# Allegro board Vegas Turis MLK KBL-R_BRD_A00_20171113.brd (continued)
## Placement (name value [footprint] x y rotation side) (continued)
PG5121  GAP-CLOSE-PWR-3-GP  [GAP-CLOSE-PWR-3]  58.35 36.5 0 top
PG5122  GAP-CLOSE-PWR-3-GP  [GAP-CLOSE-PWR-3]  58.35 35.56 0 top
PG5123  GAP-CLOSE-PWR-3-GP  [GAP-CLOSE-PWR-3]  58.35 34.62 0 top
PG5124  GAP-CLOSE-PWR-3-GP  [GAP-CLOSE-PWR-3]  58.34 33.68 0 top
PG5125  GAP-CLOSE-PWR-3-GP  [GAP-CLOSE-PWR-3]  58.1 38.89 0 bottom
PG5126  GAP-CLOSE-PWR-3-GP  [GAP-CLOSE-PWR-3]  58.09 37.94 0 bottom
PG5127  GAP-CLOSE-PWR-3-GP  [GAP-CLOSE-PWR-3]  58.09 37 0 bottom
PG5128  GAP-CLOSE-PWR-3-GP  [GAP-CLOSE-PWR-3]  58.09 36.06 0 bottom
PG5129  GAP-CLOSE-PWR-3-GP  [GAP-CLOSE-PWR-3]  58.1 35.1 0 bottom
PG5130  GAP-CLOSE-PWR-3-GP  [GAP-CLOSE-PWR-3]  58.1 34.17 0 bottom
PG5151  -  [GAP-CLOSE-PWR]  135.59 29.98 180 bottom
PG5152  -  [GAP-CLOSE-PWR]  135.59 29.22 180 bottom
PG5301  GAP-CLOSE-PWR-3-GP  [GAP-CLOSE-PWR-3]  184.97 69.77 180 bottom
PG5302  GAP-CLOSE-PWR-3-GP  [GAP-CLOSE-PWR-3]  184.97 70.54 180 bottom
PG5303  GAP-CLOSE-PWR-3-GP  [GAP-CLOSE-PWR-3]  184.96 68.83 180 bottom
PG5304  GAP-CLOSE-PWR-3-GP  [GAP-CLOSE-PWR-3]  168.03 73.97 180 bottom
PG5305  GAP-CLOSE-PWR-3-GP  [GAP-CLOSE-PWR-3]  168.03 74.73 180 bottom
PG5306  GAP-CLOSE-PWR-3-GP  [GAP-CLOSE-PWR-3]  168.03 75.49 180 bottom
PG5307  GAP-CLOSE-PWR-3-GP  [GAP-CLOSE-PWR-3]  168.03 76.25 180 bottom
PG5308  GAP-CLOSE-PWR-3-GP  [GAP-CLOSE-PWR-3]  168.03 77.01 180 bottom
PG5309  GAP-CLOSE-PWR-3-GP  [GAP-CLOSE-PWR-3]  168.03 77.01 180 top
PG5310  GAP-CLOSE-PWR-3-GP  [GAP-CLOSE-PWR-3]  175.04 71.83 180 top
PG5311  GAP-CLOSE-PWR-3-GP  [GAP-CLOSE-PWR-3]  168.03 76.25 180 top
PG5312  GAP-CLOSE-PWR-3-GP  [GAP-CLOSE-PWR-3]  168.03 75.49 180 top
PG5313  GAP-CLOSE-PWR-3-GP  [GAP-CLOSE-PWR-3]  168.03 74.73 180 top
PG5314  GAP-CLOSE-PWR-3-GP  [GAP-CLOSE-PWR-3]  168.03 73.97 180 top
PG5405  -  [GAP-CLOSE-PWR]  164.27 72.39 90 bottom
PG5406  -  [GAP-CLOSE-PWR]  163.51 72.39 90 bottom
PG5407  -  [GAP-CLOSE-PWR]  162.75 72.39 90 bottom
PG8501  -  [GAP-CLOSE-PWR]  163.61 99.63 0 bottom
PG8502  -  [GAP-CLOSE-PWR]  163.61 98.86 0 bottom
PG8503  -  [GAP-CLOSE-PWR]  163.61 98.1 0 bottom
PG8504  -  [GAP-CLOSE-PWR]  167.08 95.83 90 bottom
PG8505  -  [GAP-CLOSE-PWR]  166.32 95.83 90 bottom
PG8506  -  [GAP-CLOSE-PWR]  165.56 95.83 90 bottom
PG8507  GAP-CLOSE-PWR-3-GP  [GAP-CLOSE-PWR-3]  178.22 114.12 180 bottom
PG8508  GAP-CLOSE-PWR-3-GP  [GAP-CLOSE-PWR-3]  180.74 114.12 0 bottom
PG8509  GAP-CLOSE-PWR-3-GP  [GAP-CLOSE-PWR-3]  178.54 100.61 180 bottom
PG8510  GAP-CLOSE-PWR-3-GP  [GAP-CLOSE-PWR-3]  180.91 100.64 0 bottom
PG8511  -  [GAP-CLOSE-PWR]  163.96 119.89 0 top
PG8512  -  [GAP-CLOSE-PWR]  163.96 119.13 0 top
PG8513  -  [GAP-CLOSE-PWR]  163.96 118.37 0 top
PG8514  -  [GAP-CLOSE-PWR]  163.96 117.6 0 top
PG8515  -  [GAP-CLOSE-PWR]  163.96 116.84 0 top
PG8516  -  [GAP-CLOSE-PWR]  163.96 116.08 0 top
PG8601  -  [GAP-CLOSE-PWR]  135.13 151.55 0 bottom
PG8602  -  [GAP-CLOSE-PWR]  135.13 152.31 0 bottom
PG8603  -  [GAP-CLOSE-PWR]  148.93 150.04 0 bottom
PG8604  -  [GAP-CLOSE-PWR]  148.95 149.07 0 bottom
PG8651  GAP-CLOSE-PWR-3-GP  [GAP-CLOSE-PWR-3]  189.92 173.05 270 bottom
PG8652  GAP-CLOSE-PWR-3-GP  [GAP-CLOSE-PWR-3]  190.88 173.04 270 bottom
PG8653  GAP-CLOSE-PWR-3-GP  [GAP-CLOSE-PWR-3]  197 154.13 180 bottom
PG8655  GAP-CLOSE-PWR-3-GP  [GAP-CLOSE-PWR-3]  198.12 174.41 270 top
PL4401  COIL-4D7UH-33-GP  [L7066-1830-UH119]  139.68 163.98 270 bottom
PL4501  IND-2D2UH-46-GP-U1  [L7066-1830-UH119]  52.53 60.14 180 bottom
PL4502  IND-3D3UH-57-GP-U  [L7066-1830-UH119]  43 60.14 0 bottom
PL4701  COIL-D15UH-2-GP  [L7366-1930H158]  103.66 118.21 180 bottom
PL4801  COIL-D15UH-2-GP  [L7366-1930H158]  123.04 117.99 180 bottom
PL4802  COIL-D15UH-2-GP  [L7366-1930H158]  113.19 117.96 180 bottom
PL5001  IND-D47UH-22-GP-U  [L7066-1830-UH119]  135.87 117.97 180 bottom
PL5101  COIL-D68UH-5-GP-U  [L7066-1830-UH119]  48.68 31.52 0 bottom
PL5301  COIL-1UH-34-GP-U1  [L7066-1830-UH119]  174.2 75.41 90 bottom
PL8501  IND-D33UH-7-GP-U  [L7066-1830-UH119]  179.5 114.12 270 bottom
PL8502  IND-D33UH-7-GP-U  [L7066-1830-UH119]  179.73 100.77 270 bottom
PL8601  IND-1UH-281-GP  [L3030-3009H63]  145.5 152.33 270 bottom
PL8651  IND-D68UH-36-GP-U  [L686647-127318H119]  194.92 158.71 180 bottom
PQ4301  DMN5L06K-7-GP  [SOT23DGS2D4H48]  61.32 173.71 90 bottom
PQ4302  LMBT3904LT1G-GP  [SOT23CBE2D4H44]  57.49 173.69 90 bottom
PQ4304  LMUN5212T1G-GP  [SOT323CBE2D2H40]  82.53 160.19 0 top
PQ4305  LTA024EUB-FS8-GP  [SC70-2D2-312H44]  81.02 164.23 0 top
PQ4306  2N7002KDW-GP  [SOT-363H44]  77.63 164.72 90 top
PQ4401  AON7403-GP-U  [PPAK-8P-3232H36]  142.25 161.9 0 top
PQ4402  2N7002K-2-GP  [SOT23DGS2D4H44]  123.35 182.12 90 top
PQ4405  2N7002KDW-GP  [SOT-363H44]  120.8 169.51 180 top
PQ4406  2N7002KDW-GP  [SOT-363H44]  127.16 179.43 90 top
PQ4409  MMBT3906-7F-GP  [SOT23CBE2D4H44]  123.48 176.71 0 top
PQ4410  AON7403-GP-U  [PPAK-8P-3232H36]  117.28 163.35 90 top
PQ4412  2N7002K-2-GP  [SOT23DGS2D4H44]  119.01 175.01 180 top
PQ4415  LMUN5212T1G-GP  [SOT323CBE2D2H40]  139.73 172.62 180 top
PQ4416  LTA024EUB-FS8-GP  [SC70-2D2-312H44]  138.23 168.12 90 top
PQ8501  2N7002KDW-GP  [SOT-363H44]  161.62 104.81 270 top
PQ8604  2N7002KDW-GP  [SOT-363H44]  146.01 137.77 270 bottom
PQ8607  DMP2130L-7-GP  [SOT23DGS2D4H48]  146.25 139.4 270 top
PQ8608  2N7002K-2-GP  [SOT23DGS2D4H44]  143.34 143.11 180 top
PQ8609  PJA3419-GP  [SOT23DGS2D4H44]  145.84 141.11 90 bottom
PR4302  15KR2F-GP  [R402H16]  56.59 171.45 90 bottom
PR4303  10KR2J-L-GP  [R402H15]  60.81 171.49 270 bottom
PR4304  2K2R2J-L1-GP  [R402H16]  65.03 173.36 270 bottom
PR4305  33R2J-2-GP  [R402H16]  65.03 174.2 270 bottom
PR4306  33R2J-2-GP  [R402H16]  63.76 173.76 0 bottom
PR4307  240KR3-GP  [R603H22]  83.17 167.59 0 top
PR4308  47KR3J-L-GP  [R603H22]  83.26 164.73 0 top
PR4309  100KR2J-1-GP  [R402H16]  59.81 170 90 bottom
PR4312  100KR2J-1-GP  [R402H16]  77.68 168.35 0 top
PR4313  -  [0R0402-PAD]  76.31 167.01 270 top
PR4314  3K3R6J-GP  [R1206H28]  79.25 168.48 0 top
PR4317  -  [0R0603-PAD]  63.82 176.71 0 top
PR4401  200KR2F-L-GP  [R402H16]  138.19 175.76 270 top
PR4402  200KR2F-L-GP  [R402H16]  138.54 177.19 180 top
PR4403  95K3R2F-GP  [R402H16]  136.18 175.01 270 top
PR4404  82K5R2F-GP  [R402H16]  136.18 178.35 270 top
PR4405  147KR2F-GP  [R402H16]  138.4 179.3 270 bottom
PR4406  -  [0R0402-PAD]  136.18 177.59 90 top
PR4407  100R2F-L3-GP  [R402H16]  138.48 179.3 90 top
PR4408  0R2J-2-GP  [R402H16]  124.24 179.45 0 top
PR4409  100KR2F-L3-GP  [R402H16]  139.12 177.07 0 bottom
PR4410  7K15R2F-L-GP  [R402H16]  138.18 171.14 270 bottom
PR4411  1KR2F-L1-GP  [R402H15]  134.08 178.86 0 top
PR4412  NTC-220K-1-GP-U  [NTC-402H24-U]  138.28 170.21 90 bottom
PR4413  100KR2F-L3-GP  [R402H16]  127.92 176.53 90 top
PR4414  1MR2J-1-GP  [R402H16]  119.89 178.44 0 top
PR4415  -  [0R0402-PAD]  120.4 181.05 180 top
PR4416  18K7R2F-GP  [R402H16]  131.48 181.45 90 bottom
PR4417  100KR2J-1-GP  [R402H16]  130.26 176.74 90 top
PR4418  191KR2F-1-GP  [R402H16]  121.62 172.32 90 top
PR4420  10KR2F-L1-GP  [R402H15]  118.83 168.19 180 top
PR4422  10KR2F-L1-GP  [R402H15]  119.62 166.84 90 top
PR4426  D01R3721F-GP-U  [R3720H40]  122.66 163.63 90 top
PR4428  0R0603-PAD-1-GP-U  [0R0603-PAD-U]  131.13 171.62 180 bottom
PR4431  100KR2J-1-GP  [R402H16]  121.67 179.45 0 top
PR4434  300KR2F-L-GP  [R402H16]  133.23 178.87 180 top
PR4435  10KR2F-L1-GP  [R402H15]  133.16 180.64 270 bottom
PR4437  2R2F-GP  [R402H16]  136.46 173.68 90 top
PR4438  4D7R3F-L-GP  [R603H22]  135.12 170.93 90 bottom
PR4439  100KR2F-L3-GP  [R402H16]  138.3 177.07 0 bottom
PR4440  20KR3J-1-GP  [R603H22]  118.59 171.98 270 top
PR4441  100KR2J-1-GP  [R402H16]  119.62 165.98 270 top
PR4443  D01R3721F-GP-U  [R3720H40]  143.49 170.06 0 bottom
PR4444  1KR2J-1-GP  [R402H16]  121.32 175.8 0 top
PR4445  470KR2J-L1-GP  [R402H15]  118.41 170.89 270 top
PR4449  10KR2F-L1-GP  [R402H15]  134.84 180.64 90 bottom
PR4450  100KR2F-L3-GP  [R402H16]  135.5 181.55 270 bottom
PR4451  100KR2F-L3-GP  [R402H16]  131.5 179 90 top
PR4452  150KR2F-L-GP  [R402H16]  130.65 182.64 270 bottom
PR4453  10KR2F-L1-GP  [R402H15]  126.12 175.57 270 top
PR4454  100R5F-2-GP  [R805H24]  128.56 173.87 270 top
PR4455  680KR2F-GP  [R402H16]  122.54 179.45 180 top
PR4456  2R2F-GP  [R402H16]  138.47 173.12 0 bottom
PR4457  0R0402-PAD-1-GP  [0R0402-PAD]  139.29 173.12 0 bottom
PR4458  -  [0R0402-PAD]  130.54 182.68 90 top
PR4459  -  [0R0402-PAD]  125.94 172.34 270 top
PR4462  -  [0R0402-PAD]  123.4 179.45 0 top
PR4467  0R0402-PAD-1-GP  [0R0402-PAD]  128.12 179.59 270 bottom
PR4468  2R2F-GP  [R402H16]  128.13 178.71 270 bottom
PR4470  -  [0R0402-PAD]  133.38 181.88 180 bottom
PR4471  -  [0R0402-PAD]  134.24 181.89 180 bottom
PR4472  100KR2F-L3-GP  [R402H16]  127.89 181.37 90 top
PR4474  -  [0R0402-PAD]  131.58 177.27 180 top
PR4475  -  [0R0402-PAD]  137.67 182.13 90 bottom
PR4476  -  [0R0402-PAD]  137.67 181.31 90 bottom
PR4477  1KR2F-L1-GP  [R402H15]  128.12 175.39 270 bottom
PR4478  100KR2J-1-GP  [R402H16]  125.94 182.62 180 top
PR4481  0R2J-2-GP  [R402H16]  135.05 167.88 180 top
PR4501  0R2J-2-GP  [R402H16]  43.48 79.83 270 top
PR4502  -  [0R0402-PAD]  52.76 79.06 0 top
PR4503  -  [0R0402-PAD]  44.27 76.27 90 top
PR4504  -  [0R0402-PAD]  44.02 77.54 0 top
PR4505  -  [0R0402-PAD]  48.44 79.96 180 top
PR4512  6K65R2F-GP  [R402H16]  46.18 79.8 0 top
PR4517  127KR2F-L-GP  [R402H16]  44.91 77.54 180 top
PR4523  10KR2F-L1-GP  [R402H15]  47.04 78.94 180 top
PR4524  1D5R3-GP  [R603H22]  53.64 73.47 90 top
PR4525  0R2J-2-GP  [R402H16]  50.98 79.06 0 top
PR4526  10KR2F-2-GP  [R402H16]  49.71 80.41 90 top
PR4527  15K4R2F-GP  [R402H16]  49.71 79.45 270 top
PR4528  1D5R3-GP  [R603H22]  43.48 72.96 90 top
PR4529  2D2R5F-2-GP  [R805H24]  57.25 64.89 0 bottom
PR4530  0R2J-2-GP  [R402H16]  43.48 78.94 90 top
PR4531  127KR2F-L-GP  [R402H16]  51.87 79.06 180 top
PR4533  2D2R5F-2-GP  [R805H24]  46.8 65.63 270 bottom
PR4534  100KR2J-1-GP  [R402H16]  44.27 75.38 90 top
PR4535  0R2J-2-GP  [R402H16]  45.67 81.07 270 top
PR4601  0R0402-PAD-1-GP  [0R0402-PAD]  114.83 142.23 270 top
PR4602  0R0402-PAD-1-GP  [0R0402-PAD]  114.83 143.01 270 top
PR4603  1KR2F-L1-GP  [R402H15]  126.15 149.48 0 top
PR4604  100R2F-L3-GP  [R402H16]  121.98 149.46 0 top
PR4605  75R2F-2-GP  [R402H16]  123.38 149.46 0 top
PR4606  45D3R2F-L-GP  [R402H16]  124.76 149.48 0 top
PR4607  100R2F-L3-GP  [R402H16]  126.15 147.77 0 top
PR4608  90K9R2F-GP  [R402H16]  127.1 143.47 270 top
PR4609  10KR2F-L1-GP  [R402H15]  127.49 147.81 0 top
PR4610  1R2J-GP  [R402H16]  121.2 147.73 0 top
PR4611  NTC-10K-29-GP-U  [NTC-402H22-U]  130.9 119.06 180 bottom
PR4612  0R0402-PAD-1-GP  [0R0402-PAD]  117.33 148.3 270 top
PR4613  0R2J-L-GP  [R402H15]  114.41 147.31 270 top
PR4614  0R2J-L-GP  [R402H15]  127.09 144.26 90 bottom
PR4615  1KR2F-L1-GP  [R402H15]  116.01 145.5 90 top
PR4616  5K76R2F-2-GP  [R402H16]  127.11 142.64 270 bottom
PR4617  NTC-470K-9-GP-U  [NTC-402H24-U]  127.9 122.3 0 bottom
PR4618  11KR2F-L-GP  [R402H16]  114.47 144.72 90 top
PR4620  392R2F-GP  [R402H16]  116.69 144.61 90 top
PR4621  27K4R2F-GP  [R402H16]  129.48 143.53 270 top
PR4622  10R2F-L1-GP  [R402H16]  121.99 147.72 0 top
PR4623  0R0402-PAD-1-GP  [0R0402-PAD]  123.36 147.74 0 top
PR4624  49D9R2F-L1-GP  [R402H16]  124.72 147.75 0 top
PR4625  2K61R2F-1-GP  [R402H16]  112.82 143.74 90 top
PR4626  3K3R2F-2-GP  [R402H16]  127.1 142.66 270 top
PR4627  100R2F-L3-GP  [R402H16]  117.68 142.53 0 top
PR4628  9K31R2F-GP  [R402H16]  120.05 144.82 0 top
PR4629  88K7R2F-GP  [R402H16]  120.83 144.82 0 top
PR4630  2KR2F-L1-GP  [R402H16]  127.72 139.48 90 bottom
PR4631  100R2F-L3-GP  [R402H16]  130.47 140.08 0 bottom
PR4632  1KR2F-3-GP  [R402H16]  116.42 143.12 270 bottom
PR4633  3K01R2F-3-GP  [R402H16]  127.7 140.27 90 bottom
PR4635  1KR2F-L1-GP  [R402H15]  121.1 133.14 90 top
PR4636  499R2F-2-GP  [R402H16]  127.42 141.87 90 bottom
PR4637  1K69R2F-2-GP  [R402H16]  116.29 141.35 90 bottom
PR4638  2KR2F-L1-GP  [R402H16]  116.36 140.56 270 bottom
PR4639  100R2F-L3-GP  [R402H16]  123.81 142.78 90 top
PR4640  2K49R2F-2-L-GP  [R402H16]  116.36 138.97 90 bottom
PR4641  2K61R2F-1-GP  [R402H16]  122.96 132.12 270 top
PR4642  324R2F-GP  [R402H16]  123.82 139.63 270 top
PR4643  11KR2F-L-GP  [R402H16]  123.82 141.2 270 top
PR4644  113KR2F-1-GP  [R402H16]  119.98 141.89 90 top
PR4645  1KR2F-L1-GP  [R402H15]  129.65 139.3 0 top
PR4646  NTC-10K-29-GP-U  [NTC-402H22-U]  118.76 117.7 180 bottom
PR4647  0R0402-PAD-1-GP  [0R0402-PAD]  128.87 139.31 180 top
PR4648  274R2F-GP  [R402H16]  114.9 137.81 270 top
PR4649  0R0402-PAD-1-GP  [0R0402-PAD]  113.57 140.7 180 top
PR4650  NTC-10K-29-GP-U  [NTC-402H22-U]  99.2 118.07 180 bottom
PR4651  1KR2F-L1-GP  [R402H15]  115.27 139.17 0 top
PR4652  11KR2F-L-GP  [R402H16]  112.17 138.73 180 top
PR4653  2K61R2F-1-GP  [R402H16]  111.4 138.74 180 top
PR4654  NTC-470K-9-GP-U  [NTC-402H24-U]  97.54 126.07 180 bottom
PR4655  27K4R2F-GP  [R402H16]  122.71 136.76 270 top
PR4656  2K87R2F-1-GP  [R402H16]  121.49 135.19 90 top
PR4657  2KR2F-L1-GP  [R402H16]  120.25 137.27 0 top
PR4658  499R2F-2-GP  [R402H16]  118.66 137.27 0 top
PR4659  100R2F-L3-GP  [R402H16]  120.2 140.64 180 top
PR4660  1K91R2F-1-GP  [R402H16]  119.46 137.27 0 top
PR4661  88K7R2F-GP  [R402H16]  122.56 140.54 180 top
PR4662  4K75R2F-1-GP  [R402H16]  122.25 137.57 90 top
PR4663  100R2F-L3-GP  [R402H16]  116.88 134.75 0 top
PR4665  0R0402-PAD-1-GP  [0R0402-PAD]  129.78 141.43 180 top
PR4666  0R0402-PAD-1-GP  [0R0402-PAD]  127.15 141.08 270 top
PR4667  0R0402-PAD-1-GP  [0R0402-PAD]  116.88 136.48 0 top
PR4668  0R0402-PAD-1-GP  [0R0402-PAD]  117.37 137.73 90 top
PR4669  0R2J-L-GP  [R402H15]  126.07 138.47 90 top
PR4670  267R2F-1-GP  [R402H16]  123.82 138.86 270 top
PR4671  1K54R2F-GP  [R402H16]  127.43 141.09 90 bottom
PR4672  88K7R2F-GP  [R402H16]  127.1 144.27 270 top
PR4701  -  [0R0402-PAD]  113.27 137.01 90 top
PR4702  -  [0R0402-PAD]  107.93 129.64 0 bottom
PR4703  2D2R6J-3-GP  [R1206H28]  99.02 121.19 0 bottom
PR4704  2D2R2F-GP  [R402H16]  107.42 123.07 90 bottom
PR4705  2D2R3F-L-GP  [R603H24]  106 130.05 180 bottom
PR4706  -  [0R0402-PAD]  107.55 123.95 90 bottom
PR4708  3K65R2F-1-GP  [R402H16]  111.98 137.03 180 top
PR4712  5K11R2F-L1-GP  [R402H16]  107.09 129.64 0 bottom
PR4802  -  [0R0402-PAD]  126.02 129.38 0 bottom
PR4803  2D2R2F-GP  [R402H16]  126.66 122.75 90 bottom
PR4804  2D2R3F-L-GP  [R603H24]  124.1 129.87 180 bottom
PR4805  2D2R6J-3-GP  [R1206H28]  118.42 120.68 0 bottom
PR4806  -  [0R0402-PAD]  128.03 124.01 180 bottom
PR4808  3K65R2F-1-GP  [R402H16]  125.56 134.09 180 top
PR4809  10R2F-L1-GP  [R402H16]  124.77 134.09 0 top
PR4810  2D2R3F-L-GP  [R603H24]  115.05 129.94 180 bottom
PR4811  -  [0R0402-PAD]  116.91 129.42 0 bottom
PR4812  -  [0R0402-PAD]  116.87 123.85 90 bottom
PR4813  2D2R2F-GP  [R402H16]  116.51 122.93 90 bottom
PR4814  2D2R6J-3-GP  [R1206H28]  108.31 120.53 0 bottom
PR4815  10R2F-L1-GP  [R402H16]  127.43 136.42 180 top
PR4816  3K65R2F-1-GP  [R402H16]  123.37 133.39 180 top
PR4817  5K11R2F-L1-GP  [R402H16]  125.23 129.39 0 bottom
PR4818  5K11R2F-L1-GP  [R402H16]  116.07 129.42 0 bottom
PR4821  100KR2F-L3-GP  [R402H16]  125.41 136.53 0 top
PR4822  100KR2F-L3-GP  [R402H16]  124.62 136.52 180 top
PR4823  100KR2F-L3-GP  [R402H16]  123.84 135.47 0 top
PR4824  100KR2F-L3-GP  [R402H16]  126.66 136.42 180 top
PR5001  2D2R3F-L-GP  [R603H24]  132.24 135.24 180 top
PR5003  3K65R2F-1-GP  [R402H16]  112.77 144.72 90 top
PR5004  -  [0R0402-PAD]  115.73 143.81 90 top
PR5107  5D1R2F-GP  [R402H16]  43 20.11 0 top
PR5109  0R0402-PAD-1-GP  [0R0402-PAD]  43.83 20.11 0 top
PR5111  10KR2F-L1-GP  [R402H15]  42.65 18.37 180 top
PR5112  2D2R3F-L-GP  [R603H24]  39.36 27.45 180 top
PR5113  750KR2F-L-GP  [R402H16]  41.81 18.37 180 top
PR5114  255KR2F-GP  [R402H16]  43.28 23.23 90 top
PR5116  15K8R2F-GP  [R402H16]  35.27 19.35 90 top
PR5117  20KR2F-L3-GP  [R402H16]  37.66 19.25 180 top
PR5120  2D2R5F-2-GP  [R805H24]  46.93 24.81 0 top
PR5126  0R2J-2-GP  [R402H16]  38.51 18.37 180 top
PR5127  -  [0R0402-PAD]  39.33 18.37 180 top
PR5128  -  [0R0402-PAD]  40.97 18.37 180 top
PR5151  43K2R2F-L-GP  [R402H16]  135.65 27.58 90 bottom
PR5152  47KR2J-2-GP  [R402H16]  130.73 19.78 0 bottom
PR5153  -  [0R0402-PAD]  131.58 19.78 180 bottom
PR5154  20KR2F-L3-GP  [R402H16]  133.91 27.12 90 bottom
PR5155  10KR2F-L1-GP  [R402H15]  133.66 16.84 90 top
PR5158  -  [0R0402-PAD]  134.37 15.32 90 top
PR5301  95K3R2F-GP  [R402H16]  184.77 71.94 270 bottom
PR5302  2K55R2F-GP  [R402H16]  187.12 74.25 0 bottom
PR5303  100KR2F-L3-GP  [R402H16]  185.79 75.59 270 bottom
PR5304  10KR2F-L1-GP  [R402H15]  187.12 75.96 0 bottom
PR5305  -  [0R0402-PAD]  183.66 79.54 180 bottom
PR5306  -  [0R0402-PAD]  185.8 77.24 90 bottom
PR5308  100KR2J-1-GP  [R402H16]  184.44 79.54 180 bottom
PR5309  2D2R5F-2-GP  [R805H24]  175.66 70.92 270 bottom
PR5401  47KR2J-2-GP  [R402H16]  161.45 64.82 90 top
PR5402  100KR2F-L3-GP  [R402H16]  161.96 61.98 90 bottom
PR5403  16K5R2F-2-GP  [R402H16]  161.44 71.8 90 bottom
PR5404  13KR2F-GP  [R402H16]  160.85 71.02 90 bottom
PR5406  -  [0R0402-PAD]  161.61 65.6 270 top
PR5408  -  [0R0402-PAD]  159.67 62.78 270 bottom
PR8501  10KR2J-L-GP  [R402H15]  162.33 104.1 90 bottom
PR8502  10KR2J-L-GP  [R402H15]  163.58 103.86 0 bottom
PR8503  10KR2F-L1-GP  [R402H15]  155.64 110.86 270 bottom
PR8505  -  [0R0402-PAD]  159.04 111.09 0 top
PR8506  100KR2F-L3-GP  [R402H16]  159.09 105.21 270 bottom
PR8507  2D2R3F-L-GP  [R603H24]  165.54 104.95 270 bottom
PR8508  100KR2F-L3-GP  [R402H16]  157.12 105.44 0 bottom
PR8509  -  [0R0402-PAD]  155.83 107.07 270 bottom
PR8510  1R2F-GP  [R402H16]  168.25 107.64 90 bottom
PR8511  -  [0R0402-PAD]  156.59 107.9 270 bottom
PR8512  -  [0R0402-PAD]  154.99 109.29 270 bottom
PR8513  -  [0R0402-PAD]  155.21 110.07 270 bottom
PR8514  -  [0R0402-PAD]  157.48 110.57 270 bottom
PR8515  2D2R3F-L-GP  [R603H24]  167.37 111.94 270 bottom
PR8516  133KR2F-GP  [R402H16]  157.48 112.18 90 bottom
PR8517  3K65R2F-1-GP  [R402H16]  159.01 117.75 0 bottom
PR8518  1KR2J-1-GP  [R402H16]  155.65 111.69 270 bottom
PR8519  10KR2F-L1-GP  [R402H15]  158.2 117.75 0 bottom
PR8520  -  [0R0402-PAD]  163.87 114.06 270 top
PR8521  1R2F-GP  [R402H16]  154.72 114.91 180 bottom
PR8522  10KR2J-L-GP  [R402H15]  155.97 114.46 90 bottom
PR8523  301R2F-GP  [R402H16]  163.18 114.83 270 bottom
PR8524  100KR2F-L3-GP  [R402H16]  158.13 114.43 0 bottom
PR8525  1K13R2F-1-GP  [R402H16]  162.22 115.78 90 bottom
PR8526  33KR2F-GP  [R402H16]  163.48 116.08 180 bottom
PR8527  2KR2F-L1-GP  [R402H16]  163.87 117.34 270 bottom
PR8528  32K4R2F-1-GP  [R402H16]  164.89 114.8 270 bottom
PR8529  2K61R2F-1-GP  [R402H16]  159.83 117.75 0 bottom
PR8530  -  [0R0402-PAD]  163.87 118.18 270 bottom
PR8531  10R2J-L-GP  [R402H16]  175.28 135.81 270 top
PR8532  11KR2F-L-GP  [R402H16]  160.41 116.48 270 bottom
PR8533  NTC-10K-29-GP-U  [NTC-402H22-U]  171.18 119.52 90 bottom
PR8534  -  [0R0402-PAD]  162.42 119 270 bottom
PR8535  10R2J-L-GP  [R402H16]  167.37 134.59 270 top
PR8536  1K65R2F-GP  [R402H16]  160.8 114.4 180 bottom
PR8537  3K65R2F-1-GP  [R402H16]  158.7 116.49 90 bottom
PR8538  10KR2F-L1-GP  [R402H15]  157.23 115.17 0 bottom
PR8539  100KR2J-1-GP  [R402H16]  163.32 102.42 180 top
PR8540  1R2F-GP  [R402H16]  154.31 116.3 270 bottom
PR8541  2D2R3J-2-GP  [R603H22]  175.29 108.76 0 top
PR8542  2D2R3J-2-GP  [R603H22]  175.29 106.35 180 top
PR8543  10KR2J-L-GP  [R402H15]  156.92 116.55 90 bottom
PR8544  -  [0R0402-PAD]  157.47 111.4 90 bottom
PR8545  100R2J-L-GP  [R402H15]  161.32 102.56 270 top
PR8546  0R2J-2-GP  [R402H16]  158.19 111.09 0 top
PR8601  0R2J-2-GP  [R402H16]  145.17 143.46 270 bottom
PR8603  1KR2J-1-GP  [R402H16]  143.44 146.56 0 top
PR8606  100KR2J-1-GP  [R402H16]  142.42 140 270 bottom
PR8609  75R2F-2-GP  [R402H16]  148.37 146.81 180 top
PR8619  100KR2J-1-GP  [R402H16]  142.66 142.16 180 bottom
PR8621  -  [0R0402-PAD]  141.99 149.72 0 bottom
PR8622  30K1R2F-L-GP  [R402H16]  140.16 149.21 90 bottom
PR8623  51K1R2F-GP  [R402H16]  140.16 150.03 270 bottom
PR8624  10KR2J-L-GP  [R402H15]  138.91 149.8 0 bottom
PR8625  10KR2J-L-GP  [R402H15]  142.43 148.45 90 bottom
PR8650  10KR2J-L-GP  [R402H15]  143.01 140.31 180 top
PR8651  2K2R2J-L1-GP  [R402H16]  143.9 140.31 0 top
PR8661  10KR2J-L-GP  [R402H15]  147.35 135.81 270 bottom
PR8671  0R0402-PAD-1-GP  [0R0402-PAD]  197.75 169.32 270 bottom
PR8672  1MR2J-1-GP  [R402H16]  187.41 181.56 270 top
PR8673  100KR2J-1-GP  [R402H16]  195.08 172.33 180 bottom
PR8674  0R0603-PAD-1-GP-U  [0R0603-PAD-U]  191.5 165.66 180 bottom
PR8675  24K9R2F-L-GP  [R402H16]  197.74 167.63 90 bottom
PR8676  16K5R2F-2-GP  [R402H16]  197.75 168.45 270 bottom
PR8677  0R2J-2-GP  [R402H16]  197.34 170.67 0 bottom
PT4501  SE220U6D3VM-38-GP  [SE361414H178]  50.93 51.69 90 bottom
PT4502  SE220U6D3VM-38-GP  [SE361414H178]  38.56 51.76 90 bottom
PT4701  SE330U2VDM-4-GP  [CT7343H83]  97.34 111.48 90 bottom
PT4801  SE330U2VDM-4-GP  [CT7343H83]  127.72 111.3 270 bottom
PT4803  SE330U2VDM-4-GP  [CT7343H83]  113.52 111.13 90 bottom
PT4805  ST100U25VDM-1-GP  [CT7343H123]  97.81 132.09 90 bottom
PT4806  SE33U25VM-11-GP  [CT7343H83]  129.14 129.16 180 bottom
PT8506  SE330U2VDM-4-GP  [CT7343H83]  179.59 107.77 90 bottom
PT8507  SE330U2VDM-4-GP  [CT7343H83]  179.33 120.75 90 bottom
PT8508  SE330U2VDM-4-GP  [CT7343H83]  162.24 124.29 270 top
PT8901  SE33U25VM-11-GP  [CT7343H83]  142.98 120.09 180 bottom
PT8902  ST100U25VDM-1-GP  [CT7343H123]  135.65 131.88 270 bottom
PU4301  AON7403-GP-U  [PPAK-8P-3232H36]  87.26 168.81 270 top
PU4401  ISL95521AHRZ-T-GP  [QFN32J4-G2D7H42]  133.77 176.73 180 bottom
PU4411  SM4378NSKPC-TRG-GP  [PPAK-8PH48]  132.21 158.6 180 top
PU4412  SM4378NSKPC-TRG-GP  [PPAK-8PH48]  132.52 163.78 0 bottom
PU4501  AON7410-GP  [PPAK-8P-3232H36]  57.1 64.84 0 top
PU4502  AON7506-GP  [PPAK-8P-3232H36]  52.53 63.32 180 top
PU4503  TPS51225RUKR-GP  [QFN20-G1D75H32]  48.72 75 0 top
PU4504  AON7410-GP  [PPAK-8P-3232H36]  39.7 64.84 0 top
PU4505  AON7410-GP  [PPAK-8P-3232H36]  44.27 63.29 180 top
PU4601  ISL95859AHRTZ-T-GP  [QFN40J5-G3D6-DIFF-H34]  121.76 142.22 90 bottom
PU4701  CSD97396Q4M-GP  [DFN8J4535-G4122-U1H40]  104.2 125.71 0 bottom
PU4801  CSD97396Q4M-GP  [DFN8J4535-G4122-U1H40]  122.71 125.48 0 bottom
PU4802  CSD97396Q4M-GP  [DFN8J4535-G4122-U1H40]  113.52 125.61 0 bottom
PU5001  ISL95808HRZ-T-1-GP  [DFN8G2-G1710-U1H40]  134.21 130.98 180 top
PU5002  AON7410-GP  [PPAK-8P-3232H36]  133.47 124.72 180 bottom
PU5003  AON7410-GP  [PPAK-8P-3232H36]  137.25 123.47 0 bottom
PU5101  RT8231AGQW-GP  [QFN20-G1D75H32]  39.17 22.65 90 top
PU5102  AON7410-GP  [PPAK-8P-3232H36]  50.6 23.35 0 bottom
PU5105  AON7506-GP  [PPAK-8P-3232H36]  46.17 24.89 180 bottom
PU5151  APL5930KAI-TRG-GP  [SOIC8-G3530H63]  135.56 22.81 0 bottom
PU5301  AOZ2262QI-10-GP-U  [QFN22G4-G2PH42]  181.41 74.98 90 bottom
PU5401  APL5930KAI-TRG-GP  [SOIC8-G3530H63]  161.76 67.24 0 bottom
PU8501  ISL62771HRTZ-GP-U  [QFN40-G3D5H32]  162 109.15 270 bottom
PU8502  FDMS3600-02-RJK0215-COLAY-GP  [PPAK-8P-G5324H44-COLAY]  171.75 114.02 0 bottom
PU8503  FDMS3600-02-RJK0215-COLAY-GP  [PPAK-8P-G5324H44-COLAY]  171.74 114.04 180 top
PU8504  FDMS3600-02-RJK0215-COLAY-GP  [PPAK-8P-G5324H44-COLAY]  171.74 101.08 0 top
PU8505  FDMS3600-02-RJK0215-COLAY-GP  [PPAK-8P-G5324H44-COLAY]  171.75 101.07 180 bottom
PU8601  SYW232DFC-GP  [DFN8G2-G1711H26]  141.22 152.1 270 bottom
PU8651  SY8286RAC-GP  [QFN20Z3-G1D1H36]  194.09 166.96 270 bottom
PWR1  ACES-CON4-88-GP  [50524-00401-001]  193.3 180.9 0 bottom
Q501  DMN5L06K-7-GP  [SOT23DGS2D4H48]  83.75 74.95 270 bottom
Q502  2N7002K-2-GP  [SOT23DGS2D4H44]  80.67 73.2 0 bottom
Q1701  PJT138KA-GP  [SOT-363H44]  155.32 65.23 90 bottom
Q1702  2N7002KDW-GP  [SOT-363H44]  154.09 65.56 0 top
Q1801  2N7002KDW-GP  [SOT-363H44]  153.52 108.08 270 top
Q1901  2N7002K-2-GP  [SOT23DGS2D4H44]  165.36 74.65 0 top
Q2107  DMP2130L-7-GP  [SOT23DGS2D4H48]  177.65 28.6 180 bottom
Q2110  2N7002K-2-GP  [SOT23DGS2D4H44]  178.09 23.6 180 bottom
Q2408  2N7002K-2-GP  [SOT23DGS2D4H44]  161.07 24.06 270 bottom
Q2412  2N7002KDW-GP  [SOT-363H44]  177.54 40.34 0 bottom
Q2414  2N7002K-2-GP  [SOT23DGS2D4H44]  156.5 24.72 0 bottom
Q2505  2N7002K-2-GP  [SOT23DGS2D4H44]  39.47 41.8 0 top
Q2602  2N7002K-2-GP  [SOT23DGS2D4H44]  196.53 130.43 0 top
Q2605  2N7002K-2-GP  [SOT23DGS2D4H44]  196.61 132.41 270 bottom
Q2704  DMP2130L-7-GP  [SOT23DGS2D4H48]  165.08 5.16 180 bottom
Q2705  2N7002K-2-GP  [SOT23DGS2D4H44]  164.83 8.69 270 bottom
Q3101  DMP2130L-7-GP  [SOT23DGS2D4H48]  57.75 177.72 90 top
Q3102  2N7002K-2-GP  [SOT23DGS2D4H44]  61.44 175.54 0 top
Q5701  2N7002K-2-GP  [SOT23DGS2D4H44]  26.88 51.89 90 top
Q5702  2N7002KDW-GP  [SOT-363H44]  21.43 55.63 270 top
Q5703  LMBT3904LT1G-GP  [SOT23CBE2D4H44]  21.65 61.72 0 top
Q6301  PJA138KA-GP  [SOT23DGS2D4H44]  173.89 52.46 270 bottom
Q6401  DMN5L06K-7-GP  [SOT23DGS2D4H48]  168.76 8.97 90 bottom
Q6403  RN2418-GP  [SOT23CBE2D6H62]  186.04 12.14 90 bottom
Q6404  RN2418-GP  [SOT23CBE2D6H62]  169.96 5.56 0 bottom
Q6502  RN2418-GP  [SOT23CBE2D6H62]  181.95 93.78 180 bottom
Q6503  2N7002KDW-GP  [SOT-363H44]  145.49 21.31 90 bottom
Q6504  DMP2130L-7-GP  [SOT23DGS2D4H48]  141.92 22.04 0 bottom
Q6505  2N7002K-2-GP  [SOT23DGS2D4H44]  150.06 24.83 0 bottom
Q6701  2N7002KDW-GP  [SOT-363H44]  187.84 36.62 270 bottom
Q7901  2N7002KDW-GP  [SOT-363H44]  174.14 125.12 270 top
Q7902  2N7002K-2-GP  [SOT23DGS2D4H44]  183.92 136.66 0 top
Q7903  2N7002K-2-GP  [SOT23DGS2D4H44]  148.02 119.52 180 top
Q7904  2N7002KDW-GP  [SOT-363H44]  190.63 122.56 270 bottom
Q7905  LMBT3904LT1G-GP  [SOT23CBE2D4H44]  130.87 148.49 0 top
R401  1KR2J-1-GP  [R402H16]  97.67 102.82 270 bottom
R402  51R2J-2-GP  [R402H16]  105.89 101.16 0 bottom
R403  499R2F-2-GP  [R402H16]  97.67 101.98 270 bottom
R406  51R2J-2-GP  [R402H16]  104.99 101.16 0 bottom
R407  51R2J-2-GP  [R402H16]  110.48 105.13 180 bottom
R408  51R2J-2-GP  [R402H16]  107.04 104.99 0 bottom
R409  51R2J-2-GP  [R402H16]  107.86 104.99 0 bottom
R410  -  [0R0402-PAD]  140.14 69.1 0 bottom
R412  49D9R2F-L1-GP  [R402H16]  129.87 82.3 0 top
R413  49D9R2F-L1-GP  [R402H16]  134.17 82.86 270 top
R414  49D9R2F-L1-GP  [R402H16]  102.19 92.66 90 top
R415  49D9R2F-L1-GP  [R402H16]  103.81 91.26 180 top
R416  51R2J-2-GP  [R402H16]  106.21 105.75 0 bottom
R417  1KR2J-1-GP  [R402H16]  105.4 105.75 0 bottom
R419  1KR2J-1-GP  [R402H16]  101.7 105.37 270 bottom
R421  51R2J-2-GP  [R402H16]  103.77 105.75 0 bottom
R422  51R2J-2-GP  [R402H16]  104.58 105.75 0 bottom
R423  51R2J-2-GP  [R402H16]  102.95 105.75 0 bottom
R501  121R2F-GP  [R402H16]  129.1 82.18 180 top
R502  80D6R2F-L-GP  [R402H16]  129.22 78.39 270 top
R503  100R2F-L3-GP  [R402H16]  140.6 57.96 0 top
R504  -  [0R0402-PAD]  141.22 50.44 180 bottom
R505  470R2F-GP  [R402H16]  124.93 68.56 270 bottom
R506  220KR2F-L-GP  [R402H16]  79.3 71.88 270 bottom
R507  10KR2J-L-GP  [R402H15]  80.98 75.2 270 bottom
R601  49D9R2F-L1-GP  [R402H16]  104.96 95.33 90 top
R602  -  [0R0402-PAD]  95.9 75.78 0 bottom
R603  100KR2J-1-GP  [R402H16]  99.09 102.63 0 bottom
R604  1KR2J-1-GP  [R402H16]  90.58 94.19 90 bottom
R605  1KR2J-1-GP  [R402H16]  90.74 90.59 90 bottom
R703  -  [0R0402-PAD]  129.14 95.08 180 top
R705  -  [0R0603-PAD]  77.71 73.31 270 bottom
R709  -  [0R0402-PAD]  100.72 102.63 0 bottom
R710  100R2F-L3-GP  [R402H16]  122.36 94.95 180 top
R711  100R2F-L3-GP  [R402H16]  123.71 93.65 180 top
R712  100R2F-L3-GP  [R402H16]  87.99 90.86 180 bottom
R713  100R2F-L3-GP  [R402H16]  86.21 90.14 270 bottom
R716  100R2F-L3-GP  [R402H16]  127.26 92.41 270 top
R717  100R2F-L3-GP  [R402H16]  126.6 93.8 180 top
R718  D0002R5J-GP-U  [R805H20]  115.4 90.88 270 top
R719  D0002R5J-GP-U  [R805H20]  111.03 90.96 270 top
R720  D0002R5J-GP-U  [R805H20]  115.98 83.87 270 top
R721  0R2J-L-GP  [R402H15]  110.07 93.04 90 top
R723  54D9R2F-L1-GP  [R402H16]  100 105.37 90 bottom
R726  100R2F-L3-GP  [R402H16]  99.91 102.63 180 bottom
R727  56R2J-4-GP  [R402H16]  101.97 103.03 90 bottom
R728  220R2J-L2-GP  [R402H16]  101.97 102.21 270 bottom
R732  -  [0R0402-PAD]  103.22 102.64 0 bottom
R801  24D9R2F-L-GP  [R402H16]  112.32 93.4 180 top
R802  10KR2J-L-GP  [R402H15]  152.3 95.94 270 bottom
R806  100KR2J-1-GP  [R402H16]  27.82 74.31 90 bottom
R1101  -  [0R1206-PAD]  167.67 89.99 0 bottom
R1110  0R0603-PAD-2-GP-U  [0R0603-PAD-1-U]  155.53 80.99 270 bottom
R1117  0R0603-PAD-2-GP-U  [0R0603-PAD-1-U]  165.89 90.02 0 bottom
R1139  0R0603-PAD-2-GP-U  [0R0603-PAD-1-U]  153.16 79.8 270 top
R1204  10KR2F-L1-GP  [R402H15]  134.26 34.85 0 top
R1205  -  [0R0402-PAD]  135.08 34.86 0 top
R1206  2R2F-GP  [R402H16]  111.65 19.11 270 top
R1208  10KR2F-L1-GP  [R402H15]  134.26 33.16 180 top
R1209  24D9R2F-L-GP  [R402H16]  109.68 20.15 180 top
R1210  -  [0R0402-PAD]  135.08 33.16 180 top
R1211  10KR2F-L1-GP  [R402H15]  103.15 16.55 270 top
R1212  -  [0R0402-PAD]  101.41 16.55 90 top
R1215  240R2F-1-GP  [R402H16]  102.83 31.42 315 top
R1302  10KR2F-L1-GP  [R402H15]  106.13 18.19 180 top
R1303  -  [0R0402-PAD]  107.06 18.18 180 top
R1305  2R2F-GP  [R402H16]  99 19.33 0 top
R1306  10KR2F-L1-GP  [R402H15]  105.34 18.19 180 top
R1307  0R2J-L-GP  [R402H15]  105.65 19.48 90 top
R1309  24D9R2F-L-GP  [R402H16]  96.39 17.82 180 top
R1310  10KR2F-L1-GP  [R402H15]  103.18 17.71 270 top
R1311  -  [0R0402-PAD]  102.72 18.99 0 top
R1312  240R2F-1-GP  [R402H16]  90.33 18.8 90 top
R1501  100R2F-L3-GP  [R402H16]  133.29 94.34 0 top
R1502  200R2F-L-GP  [R402H16]  139.65 80 180 top
R1503  10KR2J-L-GP  [R402H15]  151.23 107.63 180 top
R1601  -  [0R0402-PAD]  160.12 82.42 180 bottom
R1602  -  [0R0402-PAD]  159.34 82.43 180 bottom
R1603  113R2F-GP  [R402H16]  136.51 86.64 270 top
R1604  100R2F-L3-GP  [R402H16]  137.36 94.4 180 top
R1606  10KR2J-L-GP  [R402H15]  153.19 96.64 0 top
R1607  10KR2J-L-GP  [R402H15]  145.5 64.39 180 top
R1608  10KR2J-L-GP  [R402H15]  152.89 98.2 180 bottom
R1610  10KR2J-L-GP  [R402H15]  152.4 95.68 0 top
R1701  10KR2J-L-GP  [R402H15]  145.79 105.42 180 bottom
R1702  1KR2J-1-GP  [R402H16]  153.02 66.76 90 bottom
R1704  -  [0R0402-PAD]  142.58 53.92 90 bottom
R1706  -  [0R0402-PAD]  166.9 28.79 180 bottom
R1707  10KR2J-L-GP  [R402H15]  156.13 73.15 90 bottom
R1708  -  [0R0402-PAD]  152.73 69.65 180 top
R1710  -  [0R0402-PAD]  154.82 70.25 0 bottom
R1711  0R0603-PAD-2-GP-U  [0R0603-PAD-1-U]  156.35 72.36 180 top
R1713  -  [0R0402-PAD]  156.2 76.49 180 bottom
R1715  100KR2J-1-GP  [R402H16]  156.53 77.74 270 bottom
R1716  100KR2F-L3-GP  [R402H16]  77.69 85.82 180 bottom
R1717  10KR2J-L-GP  [R402H15]  143.4 105.52 180 bottom
R1718  10KR2J-L-GP  [R402H15]  153.52 69.67 0 top
R1719  47KR2F-GP  [R402H16]  78.49 84.1 180 bottom
R1720  10KR2J-L-GP  [R402H15]  90.48 93.3 270 bottom
R1722  100KR2J-1-GP  [R402H16]  78.87 85.27 270 top
R1724  0R0805-PAD-2-GP-U  [0R0805-PAD-1-U]  163.84 86.11 90 bottom
R1726  10KR2J-L-GP  [R402H15]  157.48 64.06 0 bottom
R1727  100KR2J-1-GP  [R402H16]  153.02 65.95 270 bottom
R1728  -  [0R0402-PAD]  153.03 64.15 90 bottom
R1730  330KR2J-L1-GP  [R402H16]  158.62 68.18 180 bottom
R1731  20KR2J-L2-GP  [R402H16]  153.37 77.14 270 top
R1734  60D4R2F-GP  [R402H16]  78.48 85.82 0 bottom
R1735  0R0805-PAD-2-GP-U  [0R0805-PAD-1-U]  163.84 87.94 90 bottom
R1737  100KR2J-1-GP  [R402H16]  155.13 68.57 270 top
R1801  -  [0R0402-PAD]  137.84 62.47 180 bottom
R1802  1MR2J-1-GP  [R402H16]  121.46 102.31 0 bottom
R1803  2K7R2F-GP  [R402H16]  116.62 101.34 0 bottom
R1804  15R2F-2-GP  [R402H16]  138.67 64.56 180 bottom
R1805  2K2R2J-L1-GP  [R402H16]  153.5 105.59 90 top
R1806  -  [0R0402-PAD]  151.27 78 90 bottom
R1807  -  [0R0402-PAD]  144.48 64.66 0 bottom
R1808  -  [0R0402-PAD]  146.12 66.77 90 bottom
R1809  -  [0R0402-PAD]  144.83 67.88 0 bottom
R1810  -  [0R0402-PAD]  120.25 102.31 0 bottom
R1811  -  [0R0402-PAD]  152.4 79.62 90 bottom
R1812  -  [0R0402-PAD]  151.59 78.82 90 bottom
R1813  0R2J-L-GP  [R402H15]  136.45 64.81 0 top
R1814  -  [0R0402-PAD]  147.68 59.23 0 bottom
R1815  10MR2J-L-GP  [R402H16]  141.67 69.59 90 bottom
R1816  10KR2J-L-GP  [R402H15]  137.8 62.74 180 top
R1817  10KR2J-L-GP  [R402H15]  165.08 72.67 90 top
R1818  8K2R2F-1-GP  [R402H16]  155.28 78.77 270 top
R1819  0R2J-L-GP  [R402H15]  156.89 75.84 90 top
R1820  150KR2J-GP  [R402H16]  153.38 77.93 90 top
R1821  2K2R2J-L1-GP  [R402H16]  148.54 86.84 270 bottom
R1822  1KR2J-1-GP  [R402H16]  148.54 86.07 90 bottom
R1823  1KR2J-1-GP  [R402H16]  148.54 85.29 270 bottom
R1824  1KR2J-1-GP  [R402H16]  146.1 68.34 90 bottom
R1825  1KR2J-1-GP  [R402H16]  146.1 67.56 270 bottom
R1826  -  [0R0402-PAD]  143.96 66.11 0 top
R1827  1KR2J-1-GP  [R402H16]  153.34 80.41 90 bottom
R1828  1KR2J-1-GP  [R402H16]  145.09 61.7 90 bottom
R1829  15R2F-2-GP  [R402H16]  135.68 62.5 180 bottom
R1830  15R2F-2-GP  [R402H16]  136.72 62.48 180 bottom
R1831  15R2F-2-GP  [R402H16]  135.91 64.48 180 bottom
R1832  2K2R2J-L1-GP  [R402H16]  153.66 106.4 90 top
R1833  15R2F-2-GP  [R402H16]  137.08 64.5 180 bottom
R1834  10KR2J-L-GP  [R402H15]  183.33 48.15 270 bottom
R1835  10KR2J-L-GP  [R402H15]  179.09 50.32 0 bottom
R1901  200R2F-L-GP  [R402H16]  132.87 85.71 180 top
R1904  100KR2J-1-GP  [R402H16]  156.63 111 90 top
R1907  -  [0R0402-PAD]  128.04 69.01 0 bottom
R1908  -  [0R0402-PAD]  128.86 69.01 0 bottom
R1909  1KR2J-1-GP  [R402H16]  126.19 69 0 bottom
R1912  -  [0R0402-PAD]  127 69 0 bottom
R2001  10KR2J-L-GP  [R402H15]  156.75 74.84 270 top
R2002  10KR2J-L-GP  [R402H15]  152.7 87.19 270 top
R2003  10KR2J-L-GP  [R402H15]  154.4 76.28 90 top
R2004  10KR2J-L-GP  [R402H15]  146.27 63.64 180 bottom
R2005  10KR2J-L-GP  [R402H15]  152.71 84.81 270 top
R2006  1KR2J-1-GP  [R402H16]  144.37 60.35 270 top
R2007  1KR2J-1-GP  [R402H16]  154.91 79.43 180 bottom
R2008  10KR2J-L-GP  [R402H15]  152.73 84.02 90 top
R2015  10KR2J-L-GP  [R402H15]  140.21 66.8 0 bottom
R2016  10KR2J-L-GP  [R402H15]  141 66.8 0 bottom
R2017  10KR2J-L-GP  [R402H15]  144.74 66.11 180 top
R2018  10KR2J-L-GP  [R402H15]  145.55 66.09 0 top
R2019  1KR2J-1-GP  [R402H16]  155.72 79.43 0 bottom
R2020  10KR2J-L-GP  [R402H15]  157.01 78.18 0 top
R2022  10KR2J-L-GP  [R402H15]  155.29 79.55 90 top
R2023  10KR2J-L-GP  [R402H15]  153.78 75.42 270 top
R2024  10KR2J-L-GP  [R402H15]  153.78 74.64 90 top
R2046  51KR2J-1-GP  [R402H16]  152.33 88.53 270 top
R2048  51KR2J-1-GP  [R402H16]  152.7 86.38 270 top
R2049  51KR2J-1-GP  [R402H16]  152.71 85.59 270 top
R2101  -  [0R0402-PAD]  156.71 83.3 90 bottom
R2102  1MR2J-1-GP  [R402H16]  179.76 25.66 180 bottom
R2104  4K7R2J-2-GP  [R402H16]  175.44 27.35 180 bottom
R2107  0R0402-PAD-2-GP  [0R0402-PAD-1]  146.15 57.7 270 top
R2108  0R0603-PAD-2-GP-U  [0R0603-PAD-1-U]  153.39 92.72 0 top
R2112  0R0603-PAD-2-GP-U  [0R0603-PAD-1-U]  157.49 94.14 0 bottom
R2113  -  [0R0402-PAD]  176.32 30 90 bottom
R2114  0R2J-L-GP  [R402H15]  142.35 42.94 270 bottom
R2115  10KR2J-L-GP  [R402H15]  144.07 42.82 90 bottom
R2116  0R3J-L1-GP  [R603H22]  140.57 40.65 180 bottom
R2118  100KR2J-1-GP  [R402H16]  180.26 27.61 270 bottom
R2120  100KR2J-1-GP  [R402H16]  147.82 36.87 0 bottom
R2201  0R2J-2-GP  [R402H16]  139.02 101.97 90 bottom
R2202  0R2J-2-GP  [R402H16]  136.04 102.34 0 bottom
R2203  1MR2J-1-GP  [R402H16]  137.32 101.97 90 bottom
R2401  10KR2F-L1-GP  [R402H15]  158.59 76.01 90 top
R2402  -  [0R0402-PAD]  154.48 28.59 0 bottom
R2403  10KR2J-L-GP  [R402H15]  97.71 139.77 180 top
R2410  10KR2J-L-GP  [R402H15]  175.32 36.68 90 bottom
R2411  0R2J-L-GP  [R402H15]  147.83 38.6 0 bottom
R2412  10KR2J-L-GP  [R402H15]  174.59 42.53 0 bottom
R2414  10KR2J-L-GP  [R402H15]  162.9 29.26 90 bottom
R2415  10KR2J-L-GP  [R402H15]  172.54 51.11 180 bottom
R2416  -  [0R0402-PAD]  158.73 23.28 180 bottom
R2417  100KR2J-1-GP  [R402H16]  163.33 26.67 180 bottom
R2418  0R2J-L-GP  [R402H15]  158.71 24.98 180 bottom
R2419  -  [0R0402-PAD]  170.49 51.56 90 bottom
R2420  -  [0R0402-PAD]  164.22 28.88 180 bottom
R2421  330R2J-3-GP  [R402H16]  152.42 33.06 90 bottom
R2423  330R2J-3-GP  [R402H16]  152.36 36.43 180 top
R2424  20KR2F-L3-GP  [R402H16]  168.09 52.39 90 bottom
R2427  -  [0R0402-PAD]  166.44 52.52 0 bottom
R2428  0R2J-L-GP  [R402H15]  153.76 44.45 270 bottom
R2429  10KR2J-L-GP  [R402H15]  177.36 49.23 90 bottom
R2430  10KR2J-L-GP  [R402H15]  175.59 49.21 90 bottom
R2431  -  [0R0402-PAD]  173.62 48.92 90 bottom
R2432  1KR2J-1-GP  [R402H16]  153.75 46.84 270 bottom
R2434  100KR2J-1-GP  [R402H16]  164.62 51.93 180 bottom
R2435  -  [0R0402-PAD]  169.4 28.73 0 bottom
R2436  100KR2J-1-GP  [R402H16]  168.61 28.73 180 bottom
R2437  43R2J-GP  [R402H16]  156.07 28.59 180 bottom
R2438  -  [0R0402-PAD]  163.1 50.14 0 bottom
R2439  -  [0R0402-PAD]  163.94 50.14 0 bottom
R2441  100KR2F-L3-GP  [R402H16]  153.75 32.01 180 bottom
R2442  64K9R2F-1-GP  [R402H16]  151.59 32.27 270 bottom
R2443  10KR2F-L1-GP  [R402H15]  152.45 34.67 270 bottom
R2444  100KR2F-L3-GP  [R402H16]  152.47 37.33 90 bottom
R2445  -  [0R0402-PAD]  149.43 36.03 270 bottom
R2446  0R0603-PAD-2-GP-U  [0R0603-PAD-1-U]  159.85 50.16 180 bottom
R2448  10KR2F-L1-GP  [R402H15]  168.2 50.76 270 bottom
R2449  100KR2J-1-GP  [R402H16]  173.14 47.01 180 top
R2450  100KR2J-1-GP  [R402H16]  172.35 47.03 0 top
R2451  100KR2J-1-GP  [R402H16]  153.75 46.06 270 bottom
R2452  100KR2J-1-GP  [R402H16]  153.75 45.25 90 bottom
R2453  1KR2J-1-GP  [R402H16]  152.3 43.7 0 top
R2455  100KR2J-1-GP  [R402H16]  152.3 42 0 top
R2456  -  [0R0402-PAD]  170.42 52.35 90 bottom
R2458  -  [0R0402-PAD]  153.76 43.65 90 bottom
R2461  0R2J-2-GP  [R402H16]  178.26 47.55 90 top
R2462  0R0402-PAD-2-GP  [0R0402-PAD-1]  177.06 36.68 90 bottom
R2463  0R2J-L-GP  [R402H15]  150.77 30.3 270 top
R2464  0R2J-L-GP  [R402H15]  150.77 31.14 270 top
R2465  0R2J-L-GP  [R402H15]  162.47 27.92 180 bottom
R2466  0R2J-L-GP  [R402H15]  165.23 28.22 180 bottom
R2469  -  [0R0402-PAD]  155.55 49.13 90 bottom
R2470  -  [0R0402-PAD]  165.43 52.52 0 bottom
R2471  0R2J-L-GP  [R402H15]  153.72 36.87 180 bottom
R2472  -  [0R0402-PAD]  148.04 43.04 180 top
R2473  0R2J-2-GP  [R402H16]  148.98 43.73 0 top
R2474  -  [0R0402-PAD]  153.12 38.12 90 bottom
R2476  0R2J-L-GP  [R402H15]  152.17 34 180 top
R2478  100KR2J-1-GP  [R402H16]  165.67 29.54 90 bottom
R2479  -  [0R0402-PAD]  164.72 50.13 180 bottom
R2481  -  [0R0402-PAD]  174.88 39.62 90 bottom
R2486  0R2J-2-GP  [R402H16]  168.49 32.36 270 top
R2487  0R2J-L-GP  [R402H15]  166.73 32.49 0 top
R2489  100KR2J-1-GP  [R402H16]  158.14 29.03 270 bottom
R2491  -  [0R0402-PAD]  155.75 50.31 270 bottom
R2493  10KR2F-L1-GP  [R402H15]  155.12 41.4 180 bottom
R2495  -  [0R0402-PAD]  170.67 47.96 180 top
R2497  -  [0R0402-PAD]  152.33 40.17 0 top
R2501  4K7R2J-2-GP  [R402H16]  153.33 50.44 180 bottom
R2502  1KR2J-1-GP  [R402H16]  37.19 40.76 0 top
R2503  1K6R2F-GP  [R402H16]  40.66 38.92 0 top
R2504  10MR2J-L-GP  [R402H16]  37.19 39.04 0 top
R2505  47KR2F-GP  [R402H16]  40.66 37.16 0 top
R2507  10R2F-L1-GP  [R402H16]  154.17 50.41 180 bottom
R2602  0R2J-2-GP  [R402H16]  197.43 127.44 90 top
R2605  0R2J-2-GP  [R402H16]  90.58 139.67 90 top
R2606  -  [0R0402-PAD]  108.93 140.19 90 top
R2607  10KR2J-L-GP  [R402H15]  197.43 126.64 90 top
R2608  25K5R2F-GP  [R402H16]  196.38 125.69 270 top
R2609  24K9R2F-L-GP  [R402H16]  193.68 123.41 270 top
R2610  NTC-100K-8-GP  [NTC-603H38]  167.11 68.53 0 bottom
R2611  -  [0R0402-PAD]  192.96 125.25 180 top
R2612  -  [0R0402-PAD]  195.73 127.76 270 top
R2613  18K7R2F-GP  [R402H16]  197.82 124.62 0 top
R2614  2KR2F-L1-GP  [R402H16]  197.78 129.85 180 bottom
R2615  -  [0R0402-PAD]  196.96 129.85 0 bottom
R2701  0R0805-PAD-2-GP-U  [0R0805-PAD-1-U]  160.76 16 0 bottom
R2702  100KR2J-1-GP  [R402H16]  177.13 14.06 0 top
R2703  0R0603-PAD-2-GP-U  [0R0603-PAD-1-U]  178.4 12.74 270 bottom
R2704  -  [0R0603-PAD]  164.24 14.23 270 top
R2705  -  [0R0603-PAD]  181.16 22.68 180 top
R2706  -  [0R0603-PAD]  164.24 12.88 270 top
R2707  0R0805-PAD-2-GP-U  [0R0805-PAD-1-U]  162.62 16 0 bottom
R2708  0R0402-PAD-2-GP  [0R0402-PAD-1]  177.62 18.58 90 bottom
R2709  0R0402-PAD-2-GP  [0R0402-PAD-1]  170.31 13.98 0 bottom
R2710  100KR2J-1-GP  [R402H16]  178.12 21.64 90 bottom
R2711  200KR2F-L-GP  [R402H16]  180.29 20.7 90 bottom
R2712  -  [0R0402-PAD]  163.07 24.81 180 bottom
R2713  0R0805-PAD-2-GP-U  [0R0805-PAD-1-U]  162.31 18.85 270 bottom
R2714  0R0805-PAD-2-GP-U  [0R0805-PAD-1-U]  162.31 20.7 270 bottom
R2715  0R0603-PAD-2-GP-U  [0R0603-PAD-1-U]  169.6 24.2 0 top
R2716  100KR2J-1-GP  [R402H16]  175.59 24.39 180 bottom
R2717  100KR2J-1-GP  [R402H16]  165.64 24.69 180 top
R2718  -  [0R0402-PAD]  168.39 24.76 180 bottom
R2719  0R0402-PAD-2-GP  [0R0402-PAD-1]  166.69 14.6 180 top
R2720  22R2J-2-GP  [R402H16]  169.28 24.99 180 bottom
R2722  0R0402-PAD-2-GP  [0R0402-PAD-1]  170.07 24.99 180 bottom
R2723  22R2J-2-GP  [R402H16]  171.12 25.02 180 bottom
R2724  22R2J-2-GP  [R402H16]  173.34 24.55 180 bottom
R2734  0R0402-PAD-2-GP  [0R0402-PAD-1]  172.49 27.56 90 bottom
R2735  1KR2J-1-GP  [R402H16]  174.63 30.81 270 bottom
R2736  10KR2J-L-GP  [R402H15]  162.66 6.63 0 bottom
R2737  0R2J-2-GP  [R402H16]  162.35 9.44 270 bottom
R2738  4K7R2J-2-GP  [R402H16]  163.48 7.27 180 bottom
R2740  0R0402-PAD-2-GP  [0R0402-PAD-1]  162.38 8.63 270 bottom
R2741  0R0402-PAD-2-GP  [0R0402-PAD-1]  174.18 27.46 270 bottom
R2901  0R0603-PAD-2-GP-U  [0R0603-PAD-1-U]  153.75 15.04 0 top
R2902  0R0603-PAD-2-GP-U  [0R0603-PAD-1-U]  155.53 15.04 0 top
R2903  0R0603-PAD-2-GP-U  [0R0603-PAD-1-U]  157.41 15.47 0 top
R2904  0R0603-PAD-2-GP-U  [0R0603-PAD-1-U]  159.27 15.04 0 top
R2906  0R0603-PAD-2-GP-U  [0R0603-PAD-1-U]  183.45 17.3 270 bottom
R2907  0R0603-PAD-2-GP-U  [0R0603-PAD-1-U]  185.58 19.05 180 top
R2908  10R2F-L1-GP  [R402H16]  170.7 13.86 0 top
R2909  0R0603-PAD-2-GP-U  [0R0603-PAD-1-U]  184.26 20.98 180 top
R2910  10R2F-L1-GP  [R402H16]  172.31 13.56 0 top
R2911  0R0603-PAD-2-GP-U  [0R0603-PAD-1-U]  183.45 18.59 270 bottom
R2912  4K7R2J-2-GP  [R402H16]  173.23 13.98 0 top
R2913  4K7R2J-2-GP  [R402H16]  171.52 13.84 180 top
R2919  10KR2J-L-GP  [R402H15]  183.7 18.39 180 top
R2920  10KR2J-L-GP  [R402H15]  182.33 20.75 180 top
R2921  1KR2J-1-GP  [R402H16]  180.6 15.94 90 top
R2922  1KR2J-1-GP  [R402H16]  178.51 16.62 180 top
R2923  0R0603-PAD-2-GP-U  [0R0603-PAD-1-U]  183.41 16 90 bottom
R3101  0R0603-PAD-2-GP-U  [0R0603-PAD-1-U]  55.15 179.61 180 top
R3102  2K49R2F-2-L-GP  [R402H16]  44.35 179.29 90 top
R3103  10KR2J-L-GP  [R402H15]  53.87 174.43 270 top
R3104  -  [0R0603-PAD]  54.57 177.78 270 top
R3105  -  [0R0402-PAD]  48.17 170.11 180 top
R3106  10KR2J-L-GP  [R402H15]  62.25 179.73 90 top
R3107  100KR2J-1-GP  [R402H16]  58.76 175.52 270 top
R3109  1KR2J-1-GP  [R402H16]  53.85 173.56 90 top
R3110  -  [0R0402-PAD]  58.07 173.93 270 top
R3111  20KR2J-L2-GP  [R402H16]  62.24 177.89 270 top
R3113  15KR2J-1-GP  [R402H16]  53.85 172.7 90 top
R3301  0R0402-PAD-2-GP  [0R0402-PAD-1]  183.17 31.83 90 top
R3302  0R0402-PAD-2-GP  [0R0402-PAD-1]  183.17 31.02 90 top
R3605  0R0402-PAD-2-GP  [0R0402-PAD-1]  22.64 36.1 270 top
R3606  0R0402-PAD-2-GP  [0R0402-PAD-1]  22.64 36.88 270 top
R3607  0R0402-PAD-2-GP  [0R0402-PAD-1]  22.56 33.91 270 top
R3608  0R0402-PAD-2-GP  [0R0402-PAD-1]  22.56 34.7 270 top
R3609  0R0402-PAD-2-GP  [0R0402-PAD-1]  21.17 15.75 270 top
R3610  0R0402-PAD-2-GP  [0R0402-PAD-1]  21.17 16.54 270 top
R3611  0R0402-PAD-2-GP  [0R0402-PAD-1]  21.17 13.92 270 top
R3612  0R0402-PAD-2-GP  [0R0402-PAD-1]  21.17 14.71 270 top
R3701  0R2J-L-GP  [R402H15]  178.99 33.55 0 top
R3702  0R2J-L-GP  [R402H15]  178.23 33.55 0 top
R4002  -  [0R0402-PAD]  159.89 77.21 180 bottom
R4005  1KR2J-1-GP  [R402H16]  159.1 77.22 0 bottom
R4006  20KR2J-L2-GP  [R402H16]  67.77 86.08 180 top
R4009  10KR2J-L-GP  [R402H15]  66.48 85.42 270 top
R4010  -  [0R0402-PAD]  45.42 46.45 270 top
R4011  -  [0R0402-PAD]  175.62 41 180 bottom
R4012  0R2J-L-GP  [R402H15]  69.3 82.53 270 top
R4024  -  [0R0402-PAD]  170.14 91.04 270 top
R4025  0R0805-PAD-2-GP-U  [0R0805-PAD-1-U]  162.26 90.68 270 top
R4029  -  [0R0402-PAD]  166.54 79.68 90 bottom
R4030  -  [0R0402-PAD]  163.71 79.13 0 bottom
R4031  100KR2J-1-GP  [R402H16]  165.29 79.22 0 bottom
R4032  100KR2J-1-GP  [R402H16]  164.96 80.48 90 bottom
R4033  0R2J-2-GP  [R402H16]  164.5 79.22 0 bottom
R4034  -  [0R0402-PAD]  168.81 80.46 270 top
R4036  0R0402-PAD-2-GP  [0R0402-PAD-1]  129.01 92.41 90 top
R4048  0R0805-PAD-2-GP-U  [0R0805-PAD-1-U]  160.64 85.1 180 top
R4101  0R0805-PAD-2-GP-U  [0R0805-PAD-1-U]  156.49 104.9 0 top
R4301  -  [0R0402-PAD]  154.54 181.97 180 top
R4302  100R2J-L-GP  [R402H15]  154.92 179.99 90 top
R5501  0R0402-PAD-2-GP  [0R0402-PAD-1]  116.31 175.64 90 top
R5502  100R2J-L-GP  [R402H15]  104.3 171.2 0 top
R5503  100R2J-L-GP  [R402H15]  105.14 171.2 0 top
R5506  100KR2J-1-GP  [R402H16]  96.59 182.31 180 top
R5518  100R2J-L-GP  [R402H15]  96.85 171.52 180 bottom
R5520  0R0603-PAD-2-GP-U  [0R0603-PAD-1-U]  114.13 179.96 0 top
R5521  10KR2J-L-GP  [R402H15]  106.41 170.69 180 bottom
R5522  0R3J-L1-GP  [R603H22]  119.29 182.1 0 top
R5523  0R5J-5-GP  [R805H24]  96.39 176.3 180 top
R5524  0R2J-2-GP  [R402H16]  100.96 176.8 0 top
R5525  100R2J-L-GP  [R402H15]  105.6 170.69 180 bottom
R5526  0R2J-2-GP  [R402H16]  107.25 170.69 0 bottom
R5527  0R0603-PAD-2-GP-U  [0R0603-PAD-1-U]  114.11 182.76 0 top
R5528  100KR2J-1-GP  [R402H16]  98.1 171.95 90 bottom
R5529  100KR2J-1-GP  [R402H16]  99.8 171.95 270 bottom
R5530  -  [0R0402-PAD]  100.12 176.81 0 top
R5531  -  [0R0402-PAD]  108.79 176.22 90 top
R5532  0R5J-5-GP  [R805H24]  110.42 180.07 0 top
R5533  0R2J-L-GP  [R402H15]  112.07 170.88 90 top
R5534  0R2J-L-GP  [R402H15]  112.07 170.04 90 top
R5535  0R0402-PAD-2-GP  [0R0402-PAD-1]  115.41 173.61 90 top
R5536  0R0402-PAD-2-GP  [0R0402-PAD-1]  115.39 174.4 90 top
R5537  0R0402-PAD-2-GP  [0R0402-PAD-1]  108.55 170.26 90 bottom
R5538  0R0402-PAD-2-GP  [0R0402-PAD-1]  110.68 170.66 180 bottom
R5602  -  [0R0402-PAD]  13.22 84.3 90 bottom
R5603  -  [0R0402-PAD]  13.19 82.02 90 bottom
R5605  -  [0R0402-PAD]  27.82 75.1 270 bottom
R5606  75R2F-2-GP  [R402H16]  17.49 72.68 0 top
R5607  75R2F-2-GP  [R402H16]  17.13 78.3 0 top
R5608  75R2F-2-GP  [R402H16]  17.06 75.25 0 top
R5609  0R0603-PAD-2-GP-U  [0R0603-PAD-1-U]  20.13 74.36 0 bottom
R5610  0R0603-PAD-2-GP-U  [0R0603-PAD-1-U]  26.66 70.54 0 bottom
R5611  47R2J-2-GP  [R402H16]  12.73 80.2 0 bottom
R5612  47R2J-2-GP  [R402H16]  12.7 78.42 0 bottom
R5613  4K7R2J-2-GP  [R402H16]  26.39 82.09 0 top
R5616  4K7R2J-2-GP  [R402H16]  24.09 72.52 0 top
R5701  150R2J-L1-GP-U  [R402H16]  17.43 52.45 180 top
R5702  150R2J-L1-GP-U  [R402H16]  17.43 50.73 180 top
R5703  150R2J-L1-GP-U  [R402H16]  17.38 45.57 180 top
R5707  0R2J-2-GP  [R402H16]  25.09 53.22 270 top
R5708  150R2J-L1-GP-U  [R402H16]  17.38 47.27 180 top
R5709  10KR2J-L-GP  [R402H15]  22.09 58.56 90 top
R5710  150KR2F-L-GP  [R402H16]  20.24 59.36 90 top
R5711  200KR2F-L-GP  [R402H16]  20.24 58.54 90 top
R5712  -  [0R0402-PAD]  22.09 59.39 270 top
R5718  0R3J-L1-GP  [R603H22]  16.62 60.1 0 top
R5719  100KR2J-1-GP  [R402H16]  29.28 51.79 180 top
R6001  0R0805-PAD-2-GP-U  [0R0805-PAD-1-U]  188.86 47.63 180 bottom
R6002  -  [0R0402-PAD]  187.37 43.32 270 bottom
R6003  0R0805-PAD-2-GP-U  [0R0805-PAD-1-U]  184.78 89.98 180 bottom
R6004  0R0402-PAD-2-GP  [0R0402-PAD-1]  152.49 100.11 270 bottom
R6108  0R2J-L-GP  [R402H15]  99.9 156.95 270 top
R6109  0R2J-L-GP  [R402H15]  99.9 155.32 270 top
R6110  0R0402-PAD-2-GP  [0R0402-PAD-1]  89.71 162.29 0 top
R6111  0R0402-PAD-2-GP  [0R0402-PAD-1]  90.65 162.29 0 top
R6112  -  [0R0402-PAD]  85.22 158.18 180 top
R6113  -  [0R0402-PAD]  97.06 153.09 270 top
R6114  -  [0R0402-PAD]  97.04 152.25 270 top
R6115  0R2J-L-GP  [R402H15]  99.89 154.39 270 top
R6116  -  [0R0402-PAD]  97.03 151.43 270 top
R6117  0R0805-PAD-2-GP-U  [0R0805-PAD-1-U]  90.69 170.14 270 bottom
R6118  0R2J-L-GP  [R402H15]  98.11 159.98 270 top
R6119  0R2J-L-GP  [R402H15]  99.9 156.14 270 top
R6311  0R3J-L1-GP  [R603H22]  176.12 52.71 180 bottom
R6312  10R2F-L1-GP  [R402H16]  167.47 64.37 270 top
R6313  10R2F-L1-GP  [R402H16]  167.55 62.71 270 top
R6314  10R2F-L1-GP  [R402H16]  169.43 61.83 270 top
R6315  10R2F-L1-GP  [R402H16]  170.21 60.12 270 top
R6316  10R2F-L1-GP  [R402H16]  167.25 65.98 270 top
R6317  10R2F-L1-GP  [R402H16]  167.44 65.18 270 top
R6318  10R2F-L1-GP  [R402H16]  167.49 63.53 270 top
R6319  10R2F-L1-GP  [R402H16]  169.4 62.64 270 top
R6320  0R2J-2-GP  [R402H16]  170.29 58.49 90 top
R6321  0R2J-2-GP  [R402H16]  170.3 59.28 90 top
R6322  10R2F-L1-GP  [R402H16]  170.2 60.93 90 top
R6323  10KR2J-L-GP  [R402H15]  177.17 51.91 180 bottom
R6324  0R2J-2-GP  [R402H16]  172.11 53.75 90 bottom
R6325  0R3J-L1-GP  [R603H22]  173.49 59.11 90 top
R6401  10KR2J-L-GP  [R402H15]  167.6 6.35 0 bottom
R6404  -  [0R0402-PAD]  170.59 7.81 90 bottom
R6405  -  [0R0402-PAD]  182.85 12.34 270 bottom
R6406  274R2F-GP  [R402H16]  169.01 3.46 90 bottom
R6407  422R2F-2-GP  [R402H16]  171.68 9.72 90 bottom
R6506  1KR2J-1-GP  [R402H16]  182.73 96.17 270 bottom
R6508  -  [0R0402-PAD]  186.17 92.94 90 bottom
R6509  100KR2J-1-GP  [R402H16]  140.67 17.22 180 bottom
R6511  0R2J-2-GP  [R402H16]  145.15 23.9 180 bottom
R6512  -  [0R0402-PAD]  147.73 22.12 180 bottom
R6513  4K7R2J-2-GP  [R402H16]  148.23 16.47 270 bottom
R6514  10KR2J-L-GP  [R402H15]  141.51 17.22 180 bottom
R6515  0R2J-2-GP  [R402H16]  145.99 23.9 180 bottom
R6516  1KR2J-1-GP  [R402H16]  141.15 25.17 90 bottom
R6517  0R3J-L1-GP  [R603H22]  141.43 19.49 270 bottom
R6518  0R2J-2-GP  [R402H16]  150.75 21.12 270 top
R6519  0R2J-2-GP  [R402H16]  150.75 21.96 270 top
R6520  0R2J-2-GP  [R402H16]  143.27 24.76 180 bottom
R6521  0R0402-PAD-2-GP  [0R0402-PAD-1]  142.43 24.76 180 bottom
R6522  100R3J-4-GP  [R603H22]  149.85 22.29 90 bottom
R6601  0R3J-L1-GP  [R603H22]  186.67 15.11 180 bottom
R6701  0R0603-PAD-2-GP-U  [0R0603-PAD-1-U]  185.55 52.19 0 bottom
R6702  100KR2J-1-GP  [R402H16]  183.75 49.99 180 bottom
R6703  100KR2J-1-GP  [R402H16]  190.57 36.83 180 bottom
R6704  100KR2J-1-GP  [R402H16]  191.67 35.41 270 top
R6705  100KR2J-1-GP  [R402H16]  189.78 38.52 270 top
R6706  0R2J-2-GP  [R402H16]  185.62 36.21 180 bottom
R6707  1MR2J-1-GP  [R402H16]  186.48 36.67 90 top
R6807  0R2J-2-GP  [R402H16]  188.46 6.84 90 bottom
